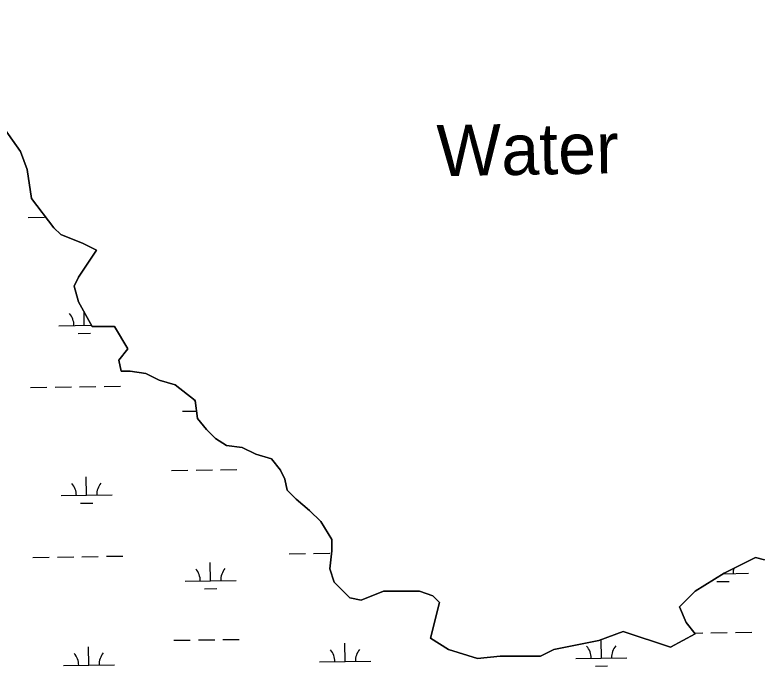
# Model space of a CAD drawing. Extents: x 3767014 to 3805179, y 361544 to 387384.
# Drawn here: x 3771779 to 3773246, y 368860 to 370135 of the extents above; entities that cross this region are included whole.
import ezdxf

# ---------------------------------------------------------------- set-up
doc = ezdxf.new("R2010")
doc.units = 0
for name, color, linetype in [('V-RIVR-IDEN', 7, 'Continuous'), ('V-TOPO-SHOR', 7, 'Continuous'), ('V-WETL-SWMP', 7, 'Continuous')]:
    doc.layers.add(name, color=color, linetype=linetype)

msp = doc.modelspace()

# ---------------------------------------------------------------- linework, layer by layer
at = {"layer": 'V-TOPO-SHOR'}
for points in [[(3771692.555, 370324.269), (3771692.555, 370306.697), (3771688.164, 370289.125), (3771679.384, 370267.16), (3771661.822, 370245.195), (3771648.651, 370240.802), (3771644.261, 370223.23), (3771653.042, 370192.48), (3771666.213, 370170.515), (3771688.164, 370130.978), (3771701.336, 370065.083), (3771701.336, 369959.652), (3771727.678, 369933.294), (3771758.41, 369911.329), (3771789.142, 369867.399), (3771802.313, 369832.255), (3771811.094, 369775.146), (3771854.998, 369718.038)], [(3771854.998, 369718.038), (3771868.169, 369704.859), (3771912.072, 369687.287), (3771938.414, 369674.108), (3771903.291, 369621.392), (3771894.511, 369603.82), (3771903.291, 369573.069), (3771929.634, 369524.747), (3771973.537, 369524.747), (3771999.879, 369480.817), (3771982.318, 369458.852), (3771986.708, 369436.888), (3772004.27, 369436.888), (3772035.002, 369432.495), (3772061.344, 369419.316), (3772092.077, 369410.53), (3772131.59, 369379.779), (3772135.98, 369344.635), (3772153.542, 369322.67), (3772171.103, 369305.098), (3772193.055, 369291.919), (3772223.787, 369287.526), (3772250.129, 369274.347), (3772280.862, 369265.561), (3772298.423, 369243.596), (3772307.204, 369226.025), (3772311.594, 369204.06), (3772329.155, 369186.488), (3772355.498, 369164.523), (3772377.449, 369142.558), (3772399.401, 369107.414), (3772399.401, 369085.449), (3772395.011, 369050.305), (3772403.791, 369023.947), (3772434.524, 368993.197), (3772456.476, 368988.804), (3772500.379, 369006.376), (3772570.625, 369006.376), (3772596.967, 368997.59), (3772610.138, 368984.411), (3772592.576, 368914.123), (3772627.699, 368892.158), (3772684.774, 368874.586), (3772728.677, 368878.979), (3772807.703, 368878.979), (3772834.045, 368892.158), (3772921.852, 368909.73), (3772970.146, 368927.302), (3773062.343, 368896.551), (3773110.637, 368922.909), (3773093.076, 368944.874), (3773079.905, 368975.625), (3773110.637, 369006.376), (3773167.712, 369041.519), (3773229.177, 369072.27), (3773246.738, 369067.877)]]:
    msp.add_lwpolyline(points, dxfattribs=at)
at = {"layer": 'V-WETL-SWMP'}
for p, q in [((3771789.142, 369867.399), (3771758.41, 369911.329)), ((3771802.313, 369832.255), (3771789.142, 369867.399)), ((3771811.094, 369775.146), (3771802.313, 369832.255)), ((3771854.998, 369718.038), (3771811.094, 369775.146)), ((3771804.412, 369737.938), (3771836.409, 369738.383)), ((3771868.169, 369704.859), (3771854.998, 369718.038)), ((3771912.072, 369687.287), (3771868.169, 369704.859)), ((3771938.414, 369674.108), (3771912.072, 369687.287)), ((3771903.291, 369621.392), (3771938.414, 369674.108)), ((3771894.511, 369603.82), (3771903.291, 369621.392)), ((3771903.291, 369573.069), (3771894.511, 369603.82)), ((3771929.634, 369524.747), (3771903.291, 369573.069)), ((3771914.199, 369526.839), (3771913.825, 369553.745)), ((3771864.204, 369526.144), (3771928.386, 369527.036)), ((3771973.537, 369524.747), (3771929.634, 369524.747)), ((3771999.879, 369480.817), (3771973.537, 369524.747)), ((3771902.415, 369511.243), (3771926.412, 369511.576)), ((3771982.318, 369458.852), (3771999.879, 369480.817)), ((3771986.708, 369436.888), (3771982.318, 369458.852)), ((3772004.27, 369436.888), (3771986.708, 369436.888)), ((3772035.002, 369432.495), (3772004.27, 369436.888)), ((3772061.344, 369419.316), (3772035.002, 369432.495)), ((3771809.033, 369405.295), (3771841.03, 369405.74)), ((3771857.029, 369405.962), (3771889.025, 369406.407)), ((3771905.024, 369406.629), (3771937.021, 369407.073)), ((3771953.019, 369407.296), (3771985.016, 369407.74)), ((3772092.077, 369410.53), (3772061.344, 369419.316)), ((3772131.59, 369379.779), (3772092.077, 369410.53)), ((3772135.98, 369344.635), (3772131.59, 369379.779)), ((3772107.025, 369358.688), (3772134.177, 369359.065)), ((3772153.542, 369322.67), (3772135.98, 369344.635)), ((3772171.103, 369305.098), (3772153.542, 369322.67)), ((3772193.055, 369291.919), (3772171.103, 369305.098)), ((3772223.787, 369287.526), (3772193.055, 369291.919)), ((3772250.129, 369274.347), (3772223.787, 369287.526)), ((3772280.862, 369265.561), (3772250.129, 369274.347)), ((3772298.423, 369243.596), (3772280.862, 369265.561)), ((3772133.218, 369243.609), (3772165.215, 369244.053)), ((3772181.214, 369244.275), (3772213.211, 369244.72)), ((3772307.204, 369226.025), (3772298.423, 369243.596)), ((3771918.82, 369194.196), (3771918.32, 369230.193)), ((3772085.223, 369242.942), (3772117.22, 369243.387)), ((3772311.594, 369204.06), (3772307.204, 369226.025)), ((3772329.155, 369186.488), (3772311.594, 369204.06)), ((3771868.825, 369193.502), (3771968.815, 369194.891)), ((3772355.498, 369164.523), (3772329.155, 369186.488)), ((3771907.035, 369178.6), (3771931.033, 369178.933)), ((3772377.449, 369142.558), (3772355.498, 369164.523)), ((3772399.401, 369107.414), (3772377.449, 369142.558)), ((3772399.401, 369085.449), (3772399.401, 369107.414)), ((3772395.011, 369050.305), (3772399.401, 369085.449)), ((3771813.654, 369072.653), (3771845.651, 369073.097)), ((3771861.649, 369073.319), (3771893.646, 369073.764)), ((3771909.645, 369073.986), (3771941.642, 369074.43)), ((3771957.64, 369074.653), (3771989.637, 369075.097)), ((3772315.514, 369079.624), (3772347.51, 369080.068)), ((3772363.509, 369080.291), (3772395.506, 369080.735)), ((3773229.177, 369072.27), (3773167.712, 369041.519)), ((3773246.738, 369067.877), (3773229.177, 369072.27)), ((3772161.641, 369026.74), (3772161.141, 369062.736)), ((3772403.791, 369023.947), (3772395.011, 369050.305)), ((3773167.712, 369041.519), (3773110.637, 369006.376)), ((3773166.376, 369040.697), (3773215.356, 369041.377)), ((3772111.646, 369026.045), (3772211.636, 369027.434)), ((3772434.524, 368993.197), (3772403.791, 369023.947)), ((3773153.576, 369025.086), (3773177.574, 369025.42)), ((3772149.857, 369011.143), (3772173.854, 369011.477)), ((3772500.379, 369006.376), (3772456.476, 368988.804)), ((3772570.625, 369006.376), (3772500.379, 369006.376)), ((3772596.967, 368997.59), (3772570.625, 369006.376)), ((3772610.138, 368984.411), (3772596.967, 368997.59)), ((3773110.637, 369006.376), (3773079.905, 368975.625)), ((3772456.476, 368988.804), (3772434.524, 368993.197)), ((3772592.576, 368914.123), (3772610.138, 368984.411)), ((3773079.905, 368975.625), (3773093.076, 368944.874)), ((3773093.076, 368944.874), (3773110.637, 368922.909)), ((3772970.146, 368927.302), (3772921.852, 368909.73)), ((3773062.343, 368896.551), (3772970.146, 368927.302)), ((3773110.637, 368922.909), (3773062.343, 368896.551)), ((3773109.395, 368924.462), (3773125.56, 368924.687)), ((3773141.558, 368924.909), (3773173.555, 368925.353)), ((3773189.554, 368925.575), (3773221.551, 368926.02)), ((3772089.844, 368910.299), (3772121.841, 368910.744)), ((3772137.839, 368910.966), (3772169.836, 368911.41)), ((3772185.834, 368911.633), (3772217.831, 368912.077)), ((3772591.703, 368917.271), (3772593.368, 368917.294)), ((3772627.699, 368892.158), (3772592.576, 368914.123)), ((3772921.852, 368909.73), (3772834.045, 368892.158)), ((3772927.16, 368875.496), (3772926.66, 368911.479)), ((3771923.441, 368861.553), (3771922.941, 368897.55)), ((3772425.3, 368868.525), (3772424.8, 368904.521)), ((3772684.774, 368874.586), (3772627.699, 368892.158)), ((3772834.045, 368892.158), (3772807.703, 368878.979)), ((3772728.677, 368878.979), (3772684.774, 368874.586)), ((3772807.703, 368878.979), (3772728.677, 368878.979)), ((3771873.446, 368860.859), (3771973.436, 368862.248)), ((3772375.305, 368867.83), (3772475.295, 368869.219)), ((3772877.165, 368874.802), (3772977.155, 368876.191)), ((3772915.375, 368859.9), (3772939.373, 368860.233))]:
    msp.add_line(p, q, dxfattribs=at)
for centre, start, end in [((3771858.955, 369526.546), 0.024037, 41.567696), ((3772101.776, 369359.09), 31.322513, 41.447833), ((3771863.576, 369193.903), 0.024037, 41.567696), ((3771974.051, 369195.438), 140.024034, 181.567693), ((3772106.397, 369026.447), 0.024037, 41.567696), ((3772216.872, 369027.982), 140.024034, 181.567693), ((3773220.591, 369041.925), 165.204265, 181.567693), ((3772370.056, 368868.232), 0.024037, 41.567696), ((3772480.531, 368869.767), 140.024034, 181.567693), ((3772871.916, 368875.203), 0.024037, 41.567696), ((3772982.391, 368876.738), 140.024034, 181.567693), ((3771868.197, 368861.261), 0.024037, 41.567696), ((3771978.672, 368862.795), 140.024034, 181.567693)]:
    msp.add_arc(centre, 35.246, start, end, dxfattribs=at)

# ---------------------------------------------------------------- texts
at = {"layer": 'V-RIVR-IDEN'}
msp.add_text('Water', height=100, rotation=0.948572, dxfattribs=at).set_placement((3772605.451, 369818.797))

doc.saveas('drawing.dxf')
